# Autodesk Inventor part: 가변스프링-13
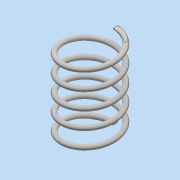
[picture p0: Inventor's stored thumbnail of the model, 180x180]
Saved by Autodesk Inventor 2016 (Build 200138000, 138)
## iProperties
Created: 2015-11
Part Number: 가변스프링-13
Material: 일반
Document SubType Name: Modeling
Designer: Administrator
Density: 1 g/cm^3
Appearance: 기본값
Mass: 1.07424 g
Surface Area: 21.7235 cm^2
Volume: 1.07424 cm^3
Author: Administrator
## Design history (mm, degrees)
sketch "스케치2"
  geometry: L1 (0, 0)-(11, 0); L2 (11, 0)-(11, 36.561); L3 (11, 36.561)-(0, 36.561); L4 (0, 36.561)-(0, 0); C1 r 1 at (11, 0)
  constraints: 8 end point, 2 parallel, 1 centre point, 1 coincident, 1 horizontal, 1 perpendicular
  dimensions: "d0" = 2 diameter of C1; "d1" = 22 diameter of L2 L4; "d2" = 36.5612 distance between parallel lines of L3 L1 (derived)
feature "코일1" sketch "스케치2" pitch "d3" = 10; turns "d5" = 5; dims "d4" = 36.5612 (= d2), "d6" = 0, angle "d7" = 90 deg, angle "d8" = 90 deg, "d9" = 0, "d10" = 0
sketch "스케치3"
  geometry: L1 (0, 12)-(0, 10) reference; 1 further point
  constraints: 1 vertical alignment
extrude "돌출1" cut sketch "스케치3" distance "d11" = 10; taper "d12" = 0 deg
node "작업 평면1"
sketch "스케치4"
  geometry: L1 (0, -1)-(0, 1) reference; 1 further point
  constraints: 1 vertical alignment
extrude "돌출2" cut sketch "스케치4" distance "d13" = 10; taper "d14" = 0 deg
node "솔리드1"
node "절단 모서리 투영1"
node "절단 모서리 투영2"
